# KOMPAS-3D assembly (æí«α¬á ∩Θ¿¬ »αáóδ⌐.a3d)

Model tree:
1. Эскиз:1
2. Операция выдавливания:1
     Расстояние 1 = 0.5; Расстояние 2 = 1

Referenced files in D:\МОДЕЛЬ ТАНКА Т90\ДЕТАЛИ\БАШНЯ\башня сварная\: ящик правый.m3d
Referenced files in D:\МОДЕЛЬ ТАНКА Т90\ДЕТАЛИ\ОБЩИЕ ДЕТАЛИ\: шарниры ящиков.m3d, замки ящиков.m3d
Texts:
  Сборка ящик правый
